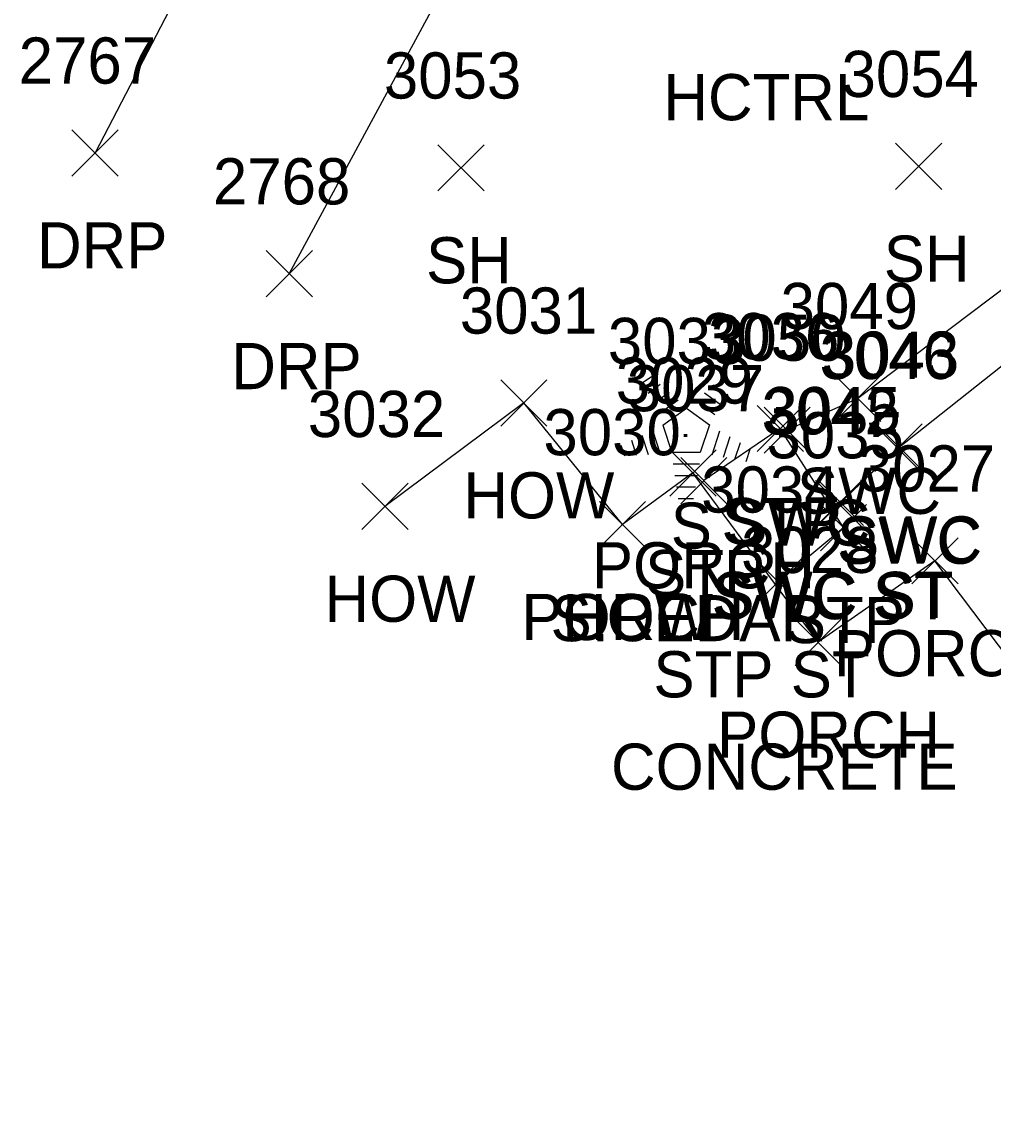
# Model space of a CAD drawing. Extents: x 1634209 to 1639641, y 608564 to 612258.
# Drawn here: x 1639305.99 to 1639348.05, y 610919.88 to 610967.04 of the extents above; entities that cross this region are included whole.
import ezdxf

# ---------------------------------------------------------------- set-up
doc = ezdxf.new("R2010")
doc.units = 0
for name, color, linetype in [('C_A', 7, 'Continuous'), ('L_A', 7, 'Continuous'), ('L_C', 7, 'Continuous'), ('L_I', 7, 'Continuous'), ('L_TIC', 7, 'Continuous'), ('LBC', 7, 'Continuous'), ('LBF', 7, 'Continuous'), ('LTC', 7, 'Continuous'), ('R_A', 7, 'Continuous'), ('R_I', 7, 'Continuous'), ('R_TIC', 7, 'Continuous'), ('RDP', 7, 'Continuous'), ('RSW', 7, 'Continuous')]:
    doc.layers.add(name, color=color, linetype=linetype)

msp = doc.modelspace()

# ---------------------------------------------------------------- linework, layer by layer
at = {"layer": 'L_TIC'}
for points in [[(1639324.003, 610959.716), (1639326.003, 610961.716)], [(1639326.003, 610959.716), (1639324.003, 610961.716)], [(1639343.82, 610959.783), (1639345.82, 610961.783)], [(1639345.82, 610959.783), (1639343.82, 610961.783)], [(1639326.723, 610949.538), (1639328.723, 610951.538)], [(1639328.723, 610949.538), (1639326.723, 610951.538)], [(1639337.827, 610948.43), (1639339.827, 610950.43)], [(1639339.827, 610948.43), (1639337.827, 610950.43)], [(1639334.049, 610946.51), (1639336.049, 610948.51)], [(1639336.049, 610946.51), (1639334.049, 610948.51)], [(1639334.518, 610946.178), (1639336.518, 610948.178)], [(1639336.518, 610946.178), (1639334.518, 610948.178)], [(1639320.71, 610945.062), (1639322.71, 610947.062)], [(1639322.71, 610945.062), (1639320.71, 610947.062)], [(1639330.997, 610944.274), (1639332.997, 610946.274)], [(1639332.997, 610944.274), (1639330.997, 610946.274)], [(1639330.997, 610944.274), (1639332.997, 610946.274)], [(1639332.997, 610944.274), (1639330.997, 610946.274)], [(1639340.569, 610944.14), (1639342.569, 610946.14)], [(1639342.569, 610944.14), (1639340.569, 610946.14)], [(1639344.524, 610942.704), (1639346.524, 610944.704)], [(1639346.524, 610942.704), (1639344.524, 610944.704)], [(1639337.744, 610941.792), (1639339.744, 610943.792)], [(1639339.744, 610941.792), (1639337.744, 610943.792)], [(1639339.471, 610939.178), (1639341.471, 610941.178)], [(1639341.471, 610939.178), (1639339.471, 610941.178)]]:
    msp.add_lwpolyline(points, dxfattribs=at)
at = {"layer": 'LBC'}
msp.add_lwpolyline([(1639331.997, 610945.274), (1639327.723, 610950.538), (1639321.71, 610946.062)], dxfattribs=at)
at = {"layer": 'LBF'}
for points in [[(1639338.744, 610942.792), (1639341.569, 610945.14), (1639338.827, 610949.43), (1639335.518, 610947.178)], [(1639358.822, 610919.876), (1639361.478, 610922.562), (1639345.524, 610943.704), (1639340.471, 610940.178), (1639335.049, 610947.51), (1639331.997, 610945.274)]]:
    msp.add_lwpolyline(points, dxfattribs=at)
at = {"layer": 'LTC'}
for p, q in [((1639332.896, 610951.432), (1639333.251, 610951.69)), ((1639336.295, 610951.673), (1639336.714, 610951.368)), ((1639333.106, 610950.967), (1639333.635, 610951.351)), ((1639335.924, 610951.324), (1639336.473, 610950.925)), ((1639333.316, 610950.501), (1639334.019, 610951.012)), ((1639333.525, 610950.035), (1639334.404, 610950.673)), ((1639335.181, 610950.628), (1639335.991, 610950.039)), ((1639335.553, 610950.976), (1639336.232, 610950.482)), ((1639333.75, 610949.58), (1639334.761, 610950.315)), ((1639334.761, 610950.315), (1639335.759, 610949.59)), ((1639333.295, 610949.361), (1639333.626, 610948.342)), ((1639333.75, 610949.58), (1639334.137, 610948.387)), ((1639335.759, 610949.59), (1639335.367, 610948.387)), ((1639336.196, 610949.319), (1639335.858, 610948.279)), ((1639331.929, 610948.711), (1639332.081, 610948.243)), ((1639332.384, 610948.928), (1639332.596, 610948.276)), ((1639332.84, 610949.145), (1639333.111, 610948.309)), ((1639336.641, 610949.068), (1639336.353, 610948.184)), ((1639337.085, 610948.818), (1639336.848, 610948.089)), ((1639335.367, 610948.387), (1639334.137, 610948.387)), ((1639337.529, 610948.568), (1639337.343, 610947.994)), ((1639335.329, 610947.887), (1639334.184, 610947.887)), ((1639335.245, 610947.387), (1639334.257, 610947.387)), ((1639335.161, 610946.887), (1639334.33, 610946.887)), ((1639335.078, 610946.387), (1639334.403, 610946.387))]:
    msp.add_line(p, q, dxfattribs=at)
at = {"layer": 'R_TIC'}
for points in [[(1639308.16, 610960.362), (1639310.16, 610962.362)], [(1639310.16, 610960.362), (1639308.16, 610962.362)], [(1639316.571, 610955.135), (1639318.571, 610957.135)], [(1639318.571, 610955.135), (1639316.571, 610957.135)], [(1639341.188, 610949.735), (1639343.188, 610951.735)], [(1639343.188, 610949.735), (1639341.188, 610951.735)], [(1639338.124, 610948.361), (1639340.124, 610950.361)], [(1639340.124, 610948.361), (1639338.124, 610950.361)], [(1639342.921, 610947.574), (1639344.921, 610949.574)], [(1639344.921, 610947.574), (1639342.921, 610949.574)], [(1639342.966, 610947.63), (1639344.966, 610949.63)], [(1639344.966, 610947.63), (1639342.966, 610949.63)], [(1639340.355, 610945.176), (1639342.355, 610947.176)], [(1639342.355, 610945.176), (1639340.355, 610947.176)], [(1639340.433, 610945.229), (1639342.433, 610947.229)], [(1639342.433, 610945.229), (1639340.433, 610947.229)]]:
    msp.add_lwpolyline(points, dxfattribs=at)
at = {"layer": 'RDP'}
for points in [[(1639328.56, 611002.564), (1639327.92, 610996.889), (1639326.492, 610993.322), (1639319.372, 610981.008), (1639309.16, 610961.362)], [(1639317.571, 610956.135), (1639326.795, 610973.228), (1639334.725, 610986.171), (1639338.638, 610988.481)]]:
    msp.add_lwpolyline(points, dxfattribs=at)
at = {"layer": 'RSW'}
for points in [[(1639341.433, 610946.229), (1639343.921, 610948.574), (1639358.164, 610959.862), (1639356.828, 610961.768), (1639342.188, 610950.735), (1639339.124, 610949.361)], [(1639341.355, 610946.176), (1639343.966, 610948.63)]]:
    msp.add_lwpolyline(points, dxfattribs=at)

# ---------------------------------------------------------------- texts
at = {"layer": 'C_A'}
msp.add_text('HCTRL', height=2, dxfattribs=at).set_placement((1639333.767, 610962.776))
at = {"layer": 'L_A'}
for s, p in [('SH', (1639323.491, 610955.716)), ('SH', (1639343.308, 610955.783)), ('HOW', (1639325.109, 610945.538)), ('STP', (1639336.284, 610944.43)), ('S', (1639334.087, 610944.224)), ('PORCH', (1639330.671, 610942.51)), ('STP', (1639332.975, 610942.178)), ('HOW', (1639319.096, 610941.062)), ('PORCH', (1639327.619, 610940.274)), ('HOW', (1639329.383, 610940.274)), ('STP', (1639339.026, 610940.14)), ('PORCH', (1639341.146, 610938.704)), ('STP ST', (1639333.335, 610937.792)), ('PORCH', (1639336.093, 610935.178))]:
    msp.add_text(s, height=2, dxfattribs=at).set_placement(p)
at = {"layer": 'L_C'}
for s, p in [('S.CEDAR', (1639328.882, 610940.224)), ('CONCRETE', (1639331.5, 610933.792))]:
    msp.add_text(s, height=2, dxfattribs=at).set_placement(p)
at = {"layer": 'L_I'}
for s, p in [('3053', (1639321.665, 610963.716)), ('3054', (1639341.482, 610963.783)), ('3031', (1639324.952, 610953.538)), ('3036', (1639335.434, 610952.43)), ('3033', (1639331.363, 610952.224)), ('3029', (1639331.703, 610950.51)), ('3037', (1639332.18, 610950.178)), ('3032', (1639318.372, 610949.062)), ('3030', (1639328.572, 610948.274)), ('3030', (1639328.572, 610948.274)), ('3035', (1639338.23, 610948.14)), ('3027', (1639342.185, 610946.704)), ('3034', (1639335.406, 610945.792)), ('3028', (1639337.133, 610943.178))]:
    msp.add_text(s, height=2, dxfattribs=at).set_placement(p)
at = {"layer": 'LTC'}
msp.add_text('.', height=1.037, rotation=270, dxfattribs=at).set_placement((1639334.644, 610949.328))
at = {"layer": 'R_A'}
for s, p in [('DRP', (1639306.648, 610956.362)), ('DRP', (1639315.059, 610951.135)), ('SWC', (1639339.55, 610945.735)), ('SWC', (1639336.486, 610944.361)), ('SWC', (1639341.283, 610943.574)), ('SWC', (1639341.328, 610943.63)), ('SWC ST', (1639335.852, 610941.176)), ('SWC ST', (1639335.93, 610941.229))]:
    msp.add_text(s, height=2, dxfattribs=at).set_placement(p)
at = {"layer": 'R_I'}
for s, p in [('2767', (1639305.853, 610964.362)), ('2768', (1639314.264, 610959.135)), ('3049', (1639338.842, 610953.735)), ('3050', (1639335.699, 610952.361)), ('3046', (1639340.528, 610951.574)), ('3043', (1639340.627, 610951.63)), ('3042', (1639338.017, 610949.176)), ('3045', (1639338.095, 610949.229))]:
    msp.add_text(s, height=2, dxfattribs=at).set_placement(p)

doc.saveas('drawing.dxf')
